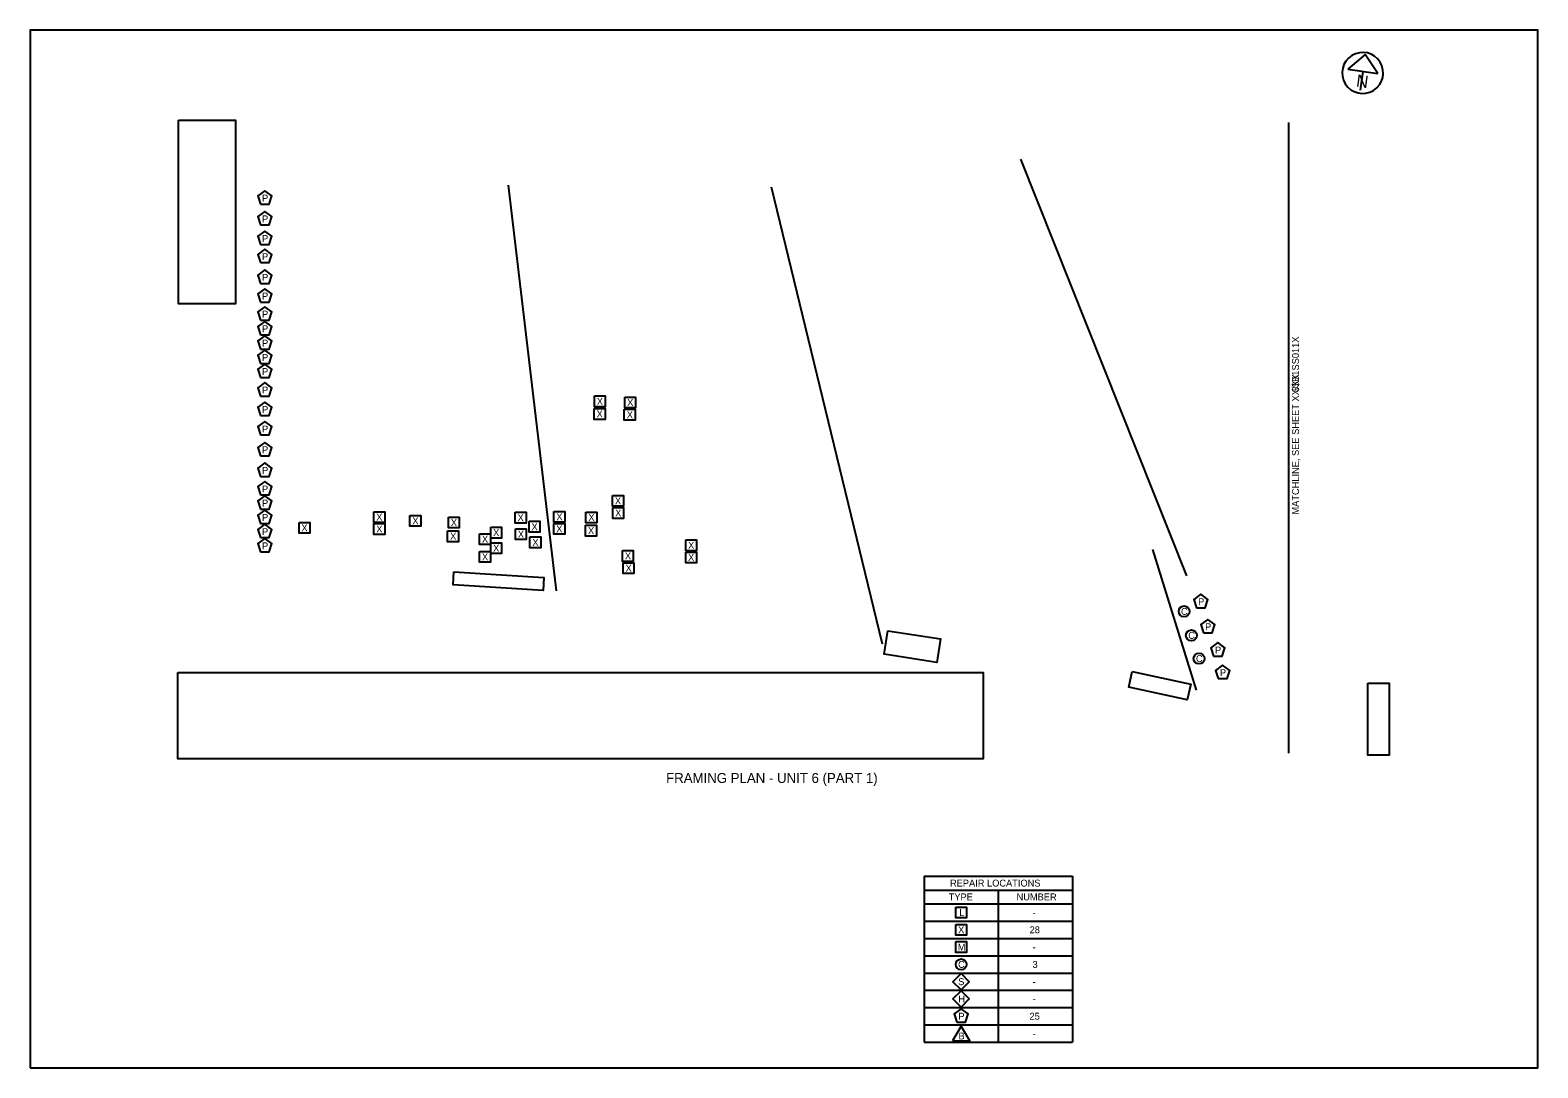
# Model space of a CAD drawing. Extents: x 100 to 130.5, y 100 to 121.
import ezdxf

# ---------------------------------------------------------------- set-up
doc = ezdxf.new("R2010")
doc.units = 0
for name, color, linetype in [('BR_P_Gen_Text', 7, 'Continuous'), ('BR_X_Sub_Centerline', 7, 'Continuous'), ('BR_X_Sub_Text', 7, 'Continuous'), ('SC_Scratch1', 7, 'Continuous'), ('SH_Data', 7, 'Continuous'), ('SH_Masking', 7, 'Continuous')]:
    doc.layers.add(name, color=color, linetype=linetype)

msp = doc.modelspace()

# ---------------------------------------------------------------- linework, layer by layer
at = {"layer": 'BR_P_Gen_Text'}
for p, q in [((125.457, 119.134), (125.457, 106.366)), ((118.083, 103.879), (118.083, 100.519)), ((118.083, 103.879), (121.083, 103.879)), ((121.083, 103.879), (121.083, 100.519)), ((118.083, 103.599), (121.083, 103.599)), ((119.583, 103.599), (119.583, 100.519)), ((118.083, 103.319), (121.083, 103.319)), ((118.083, 102.969), (121.083, 102.969)), ((118.083, 102.619), (121.083, 102.619)), ((118.083, 102.269), (121.083, 102.269)), ((118.083, 101.919), (121.083, 101.919)), ((118.083, 101.569), (121.083, 101.569)), ((118.083, 101.219), (121.083, 101.219)), ((118.083, 100.869), (121.083, 100.869)), ((118.083, 100.519), (121.083, 100.519))]:
    msp.add_line(p, q, dxfattribs=at)
for points in [[(104.659, 117.48), (104.835, 117.48), (104.89, 117.647), (104.747, 117.751), (104.604, 117.647)], [(104.659, 117.058), (104.835, 117.058), (104.89, 117.226), (104.747, 117.33), (104.604, 117.226)], [(104.659, 116.661), (104.835, 116.661), (104.89, 116.829), (104.747, 116.933), (104.604, 116.829)], [(104.659, 116.295), (104.835, 116.295), (104.89, 116.463), (104.747, 116.566), (104.604, 116.463)], [(104.659, 115.876), (104.835, 115.876), (104.89, 116.043), (104.747, 116.147), (104.604, 116.043)], [(104.659, 115.496), (104.835, 115.496), (104.89, 115.664), (104.747, 115.768), (104.604, 115.664)], [(104.659, 115.132), (104.835, 115.132), (104.89, 115.299), (104.747, 115.403), (104.604, 115.299)], [(104.659, 114.835), (104.835, 114.835), (104.89, 115.003), (104.747, 115.107), (104.604, 115.003)], [(104.659, 114.544), (104.835, 114.544), (104.89, 114.712), (104.747, 114.816), (104.604, 114.712)], [(104.659, 114.255), (104.835, 114.255), (104.89, 114.422), (104.747, 114.526), (104.604, 114.422)], [(104.659, 113.969), (104.835, 113.969), (104.89, 114.136), (104.747, 114.24), (104.604, 114.136)], [(104.659, 113.595), (104.835, 113.595), (104.89, 113.763), (104.747, 113.867), (104.604, 113.763)], [(104.659, 113.202), (104.835, 113.202), (104.89, 113.369), (104.747, 113.473), (104.604, 113.369)], [(111.414, 113.598), (111.634, 113.598), (111.634, 113.378), (111.414, 113.378)], [(112.028, 113.575), (112.248, 113.575), (112.248, 113.355), (112.028, 113.355)], [(111.41, 113.344), (111.63, 113.344), (111.63, 113.124), (111.41, 113.124)], [(112.02, 113.327), (112.24, 113.327), (112.24, 113.107), (112.02, 113.107)], [(104.659, 112.808), (104.835, 112.808), (104.89, 112.976), (104.747, 113.079), (104.604, 112.976)], [(104.659, 112.385), (104.835, 112.385), (104.89, 112.553), (104.747, 112.657), (104.604, 112.553)], [(104.659, 111.97), (104.835, 111.97), (104.89, 112.137), (104.747, 112.241), (104.604, 112.137)], [(104.659, 111.594), (104.835, 111.594), (104.89, 111.762), (104.747, 111.865), (104.604, 111.762)], [(104.659, 111.307), (104.835, 111.307), (104.89, 111.475), (104.747, 111.579), (104.604, 111.475)], [(111.781, 111.584), (112.001, 111.584), (112.001, 111.364), (111.781, 111.364)], [(111.786, 111.339), (112.006, 111.339), (112.006, 111.119), (111.786, 111.119)], [(104.659, 111.017), (104.835, 111.017), (104.89, 111.185), (104.747, 111.289), (104.604, 111.185)], [(105.439, 111.038), (105.659, 111.038), (105.659, 110.818), (105.439, 110.818)], [(106.952, 111.255), (107.172, 111.255), (107.172, 111.035), (106.952, 111.035)], [(107.681, 111.18), (107.901, 111.18), (107.901, 110.96), (107.681, 110.96)], [(108.46, 111.145), (108.68, 111.145), (108.68, 110.925), (108.46, 110.925)], [(109.811, 111.243), (110.031, 111.243), (110.031, 111.023), (109.811, 111.023)], [(110.092, 111.06), (110.312, 111.06), (110.312, 110.84), (110.092, 110.84)], [(110.596, 111.262), (110.816, 111.262), (110.816, 111.042), (110.596, 111.042)], [(111.242, 111.248), (111.462, 111.248), (111.462, 111.028), (111.242, 111.028)], [(104.659, 110.73), (104.835, 110.73), (104.89, 110.897), (104.747, 111.001), (104.604, 110.897)], [(106.952, 111.015), (107.172, 111.015), (107.172, 110.795), (106.952, 110.795)], [(108.446, 110.868), (108.666, 110.868), (108.666, 110.648), (108.446, 110.648)], [(109.091, 110.809), (109.311, 110.809), (109.311, 110.589), (109.091, 110.589)], [(109.317, 110.942), (109.537, 110.942), (109.537, 110.722), (109.317, 110.722)], [(109.816, 110.909), (110.036, 110.909), (110.036, 110.689), (109.816, 110.689)], [(110.111, 110.743), (110.331, 110.743), (110.331, 110.523), (110.111, 110.523)], [(110.594, 111.017), (110.814, 111.017), (110.814, 110.797), (110.594, 110.797)], [(111.235, 110.982), (111.455, 110.982), (111.455, 110.762), (111.235, 110.762)], [(104.659, 110.441), (104.835, 110.441), (104.89, 110.609), (104.747, 110.713), (104.604, 110.609)], [(109.091, 110.451), (109.311, 110.451), (109.311, 110.231), (109.091, 110.231)], [(109.317, 110.626), (109.537, 110.626), (109.537, 110.406), (109.317, 110.406)], [(111.981, 110.47), (112.201, 110.47), (112.201, 110.25), (111.981, 110.25)], [(113.261, 110.685), (113.481, 110.685), (113.481, 110.465), (113.261, 110.465)], [(113.261, 110.439), (113.481, 110.439), (113.481, 110.219), (113.261, 110.219)], [(111.995, 110.223), (112.215, 110.223), (112.215, 110.003), (111.995, 110.003)], [(123.595, 109.311), (123.771, 109.311), (123.826, 109.479), (123.683, 109.583), (123.541, 109.479)], [(123.737, 108.805), (123.914, 108.805), (123.968, 108.973), (123.826, 109.076), (123.683, 108.973)], [(123.938, 108.334), (124.114, 108.334), (124.169, 108.501), (124.026, 108.605), (123.883, 108.501)], [(124.036, 107.876), (124.212, 107.876), (124.267, 108.044), (124.124, 108.148), (123.981, 108.044)], [(118.723, 103.254), (118.943, 103.254), (118.943, 103.034), (118.723, 103.034)], [(118.723, 102.904), (118.943, 102.904), (118.943, 102.684), (118.723, 102.684)], [(118.723, 102.554), (118.943, 102.554), (118.943, 102.334), (118.723, 102.334)], [(118.833, 101.909), (118.998, 101.744), (118.833, 101.579), (118.668, 101.744)], [(118.833, 101.559), (118.998, 101.394), (118.833, 101.229), (118.668, 101.394)], [(118.745, 100.923), (118.922, 100.923), (118.976, 101.091), (118.833, 101.194), (118.691, 101.091)], [(118.66, 100.544), (119.007, 100.544), (118.833, 100.844)]]:
    msp.add_lwpolyline(points, close=True, dxfattribs=at)
for centre in [(123.344, 109.237), (123.491, 108.752), (123.647, 108.283), (118.833, 102.094)]:
    msp.add_circle(centre, 0.11, dxfattribs=at)
at = {"layer": 'BR_X_Sub_Centerline'}
for p, q in [((120.031, 118.39), (123.392, 109.955)), ((110.645, 109.651), (109.679, 117.86)), ((117.24, 108.575), (114.995, 117.82)), ((123.598, 107.64), (122.712, 110.488))]:
    msp.add_line(p, q, dxfattribs=at)
at = {"layer": 'BR_X_Sub_Text'}
for points in [[(108.573, 110.036), (110.394, 109.926), (110.378, 109.663), (108.557, 109.773)], [(117.35, 108.847), (118.416, 108.679), (118.341, 108.201), (117.274, 108.369)], [(122.296, 108.021), (123.477, 107.762), (123.407, 107.445), (122.227, 107.703)]]:
    msp.add_lwpolyline(points, close=True, dxfattribs=at)
at = {"layer": 'SC_Scratch1'}
msp.add_lwpolyline([(100, 100), (130.5, 100), (130.5, 121), (100, 121)], close=True, dxfattribs=at)
at = {"layer": 'SH_Data'}
for p, q in [((127.008, 120.504), (126.657, 120.208)), ((127.266, 120.124), (127.008, 120.504)), ((126.657, 120.208), (127.266, 120.124)), ((126.961, 120.166), (126.908, 119.783))]:
    msp.add_line(p, q, dxfattribs=at)
msp.add_arc((126.957, 120.134), 0.415, 121.8974, 121.8808, dxfattribs=at)
at = {"layer": 'SH_Masking'}
for points in [[(103, 119.181), (104.153, 119.181), (104.153, 115.464), (103, 115.464)], [(102.985, 107.998), (119.278, 107.998), (119.278, 106.251), (102.985, 106.251)], [(127.059, 107.783), (127.492, 107.783), (127.492, 106.325), (127.059, 106.325)]]:
    msp.add_lwpolyline(points, close=True, dxfattribs=at)

# ---------------------------------------------------------------- texts
at = {"layer": 'BR_P_Gen_Text'}
for s, height, p in [('P', 0.14, (104.691, 117.531)), ('P', 0.14, (104.691, 117.11)), ('P', 0.14, (104.691, 116.713)), ('P', 0.14, (104.691, 116.346)), ('P', 0.14, (104.691, 115.927)), ('P', 0.14, (104.691, 115.548)), ('P', 0.14, (104.691, 115.183)), ('P', 0.14, (104.691, 114.887)), ('P', 0.14, (104.691, 114.596)), ('P', 0.14, (104.691, 114.306)), ('P', 0.14, (104.691, 114.02)), ('P', 0.14, (104.691, 113.647)), ('X', 0.14, (111.463, 113.418)), ('X', 0.14, (112.077, 113.395)), ('P', 0.14, (104.691, 113.253)), ('X', 0.14, (111.459, 113.164)), ('X', 0.14, (112.069, 113.147)), ('P', 0.14, (104.691, 112.859)), ('P', 0.14, (104.691, 112.437)), ('P', 0.14, (104.691, 112.021)), ('P', 0.14, (104.691, 111.645)), ('P', 0.14, (104.691, 111.359)), ('X', 0.14, (111.83, 111.404)), ('P', 0.14, (104.691, 111.069)), ('X', 0.14, (107.002, 111.075)), ('X', 0.14, (107.731, 111)), ('X', 0.14, (108.51, 110.965)), ('X', 0.14, (109.86, 111.063)), ('X', 0.14, (110.142, 110.88)), ('X', 0.14, (110.645, 111.082)), ('X', 0.14, (111.292, 111.068)), ('X', 0.14, (111.835, 111.159)), ('P', 0.14, (104.691, 110.781)), ('X', 0.14, (105.488, 110.858)), ('X', 0.14, (107.002, 110.835)), ('X', 0.14, (108.496, 110.688)), ('X', 0.14, (109.14, 110.629)), ('X', 0.14, (109.366, 110.762)), ('X', 0.14, (109.866, 110.729)), ('X', 0.14, (110.643, 110.837)), ('X', 0.14, (111.285, 110.802)), ('P', 0.14, (104.691, 110.493)), ('X', 0.14, (109.14, 110.271)), ('X', 0.14, (109.366, 110.446)), ('X', 0.14, (110.16, 110.563)), ('X', 0.14, (112.031, 110.29)), ('X', 0.14, (113.31, 110.505)), ('X', 0.14, (112.045, 110.043)), ('X', 0.14, (113.31, 110.259)), ('P', 0.14, (123.627, 109.363)), ('C', 0.14, (123.281, 109.167)), ('P', 0.14, (123.769, 108.856)), ('C', 0.14, (123.428, 108.682)), ('C', 0.14, (123.584, 108.213)), ('P', 0.14, (123.97, 108.385)), ('P', 0.14, (124.068, 107.928)), ('FRAMING PLAN - UNIT 6 (PART 1)', 0.2, (112.865, 105.766)), ('REPAIR LOCATIONS', 0.14, (118.608, 103.669)), ('TYPE', 0.14, (118.582, 103.389)), ('NUMBER', 0.14, (119.955, 103.389)), ('L', 0.14, (118.795, 103.074)), ('-', 0.14, (120.28, 103.074)), ('X', 0.14, (118.773, 102.724)), ('28', 0.14, (120.219, 102.724)), ('M', 0.14, (118.765, 102.374)), ('-', 0.14, (120.28, 102.374)), ('C', 0.14, (118.771, 102.024)), ('3', 0.14, (120.277, 102.024)), ('S', 0.14, (118.775, 101.674)), ('-', 0.14, (120.28, 101.674)), ('H', 0.14, (118.777, 101.324)), ('-', 0.14, (120.28, 101.324)), ('P', 0.14, (118.777, 100.974)), ('25', 0.14, (120.217, 100.974)), ('B', 0.14, (118.779, 100.574)), ('-', 0.14, (120.28, 100.624))]:
    msp.add_text(s, height=height, dxfattribs=at).set_placement(p)
for s, p in [('$$B1SS011X', (125.667, 113.675)), ('MATCHLINE, SEE SHEET XX/XX', (125.667, 111.197))]:
    msp.add_text(s, height=0.14, rotation=90, dxfattribs=at).set_placement(p)
at = {"layer": 'SH_Data'}
msp.add_text('N', height=0.25, rotation=352.1175, dxfattribs=at).set_placement((126.814, 119.859))

doc.saveas('drawing.dxf')
